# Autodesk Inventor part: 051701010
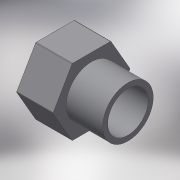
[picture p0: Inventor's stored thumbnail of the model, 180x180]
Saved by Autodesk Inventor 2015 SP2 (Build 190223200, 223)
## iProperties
Created: 2017-10
Part Number: 051701010
Material: Generic
Description: PLASSON THREADED PLUG PVC 1"
Document SubType Name: Modeling
Designer: KIM
Density: 1 g/cm^3
Appearance: Default
Author: KIM
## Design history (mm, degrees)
derived "051701.ipt"
feature "Solid1::051701.ipt"
tag "TaggingFeature1"
body "Solid1"
other parameters: "d0" = 35, "d1" = 33.249, "d2" = 1, "d3" = 12, "d4" = 36, "d6" = 26.5992, "d9" = 12, "d10" = 0, "d18" = 0.36, "d20" = 24.5, "R_" = 33.249, "C_" = 36, "B_" = 12, "H_" = 35
